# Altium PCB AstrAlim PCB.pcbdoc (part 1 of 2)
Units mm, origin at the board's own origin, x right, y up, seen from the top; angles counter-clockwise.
Board outline 112.02 x 78.49 mm, 4 copper layers (Top Layer, Inner1, Inner2, Bottom Layer); 151 components, 74 nets, 446 pads, 97 vias.
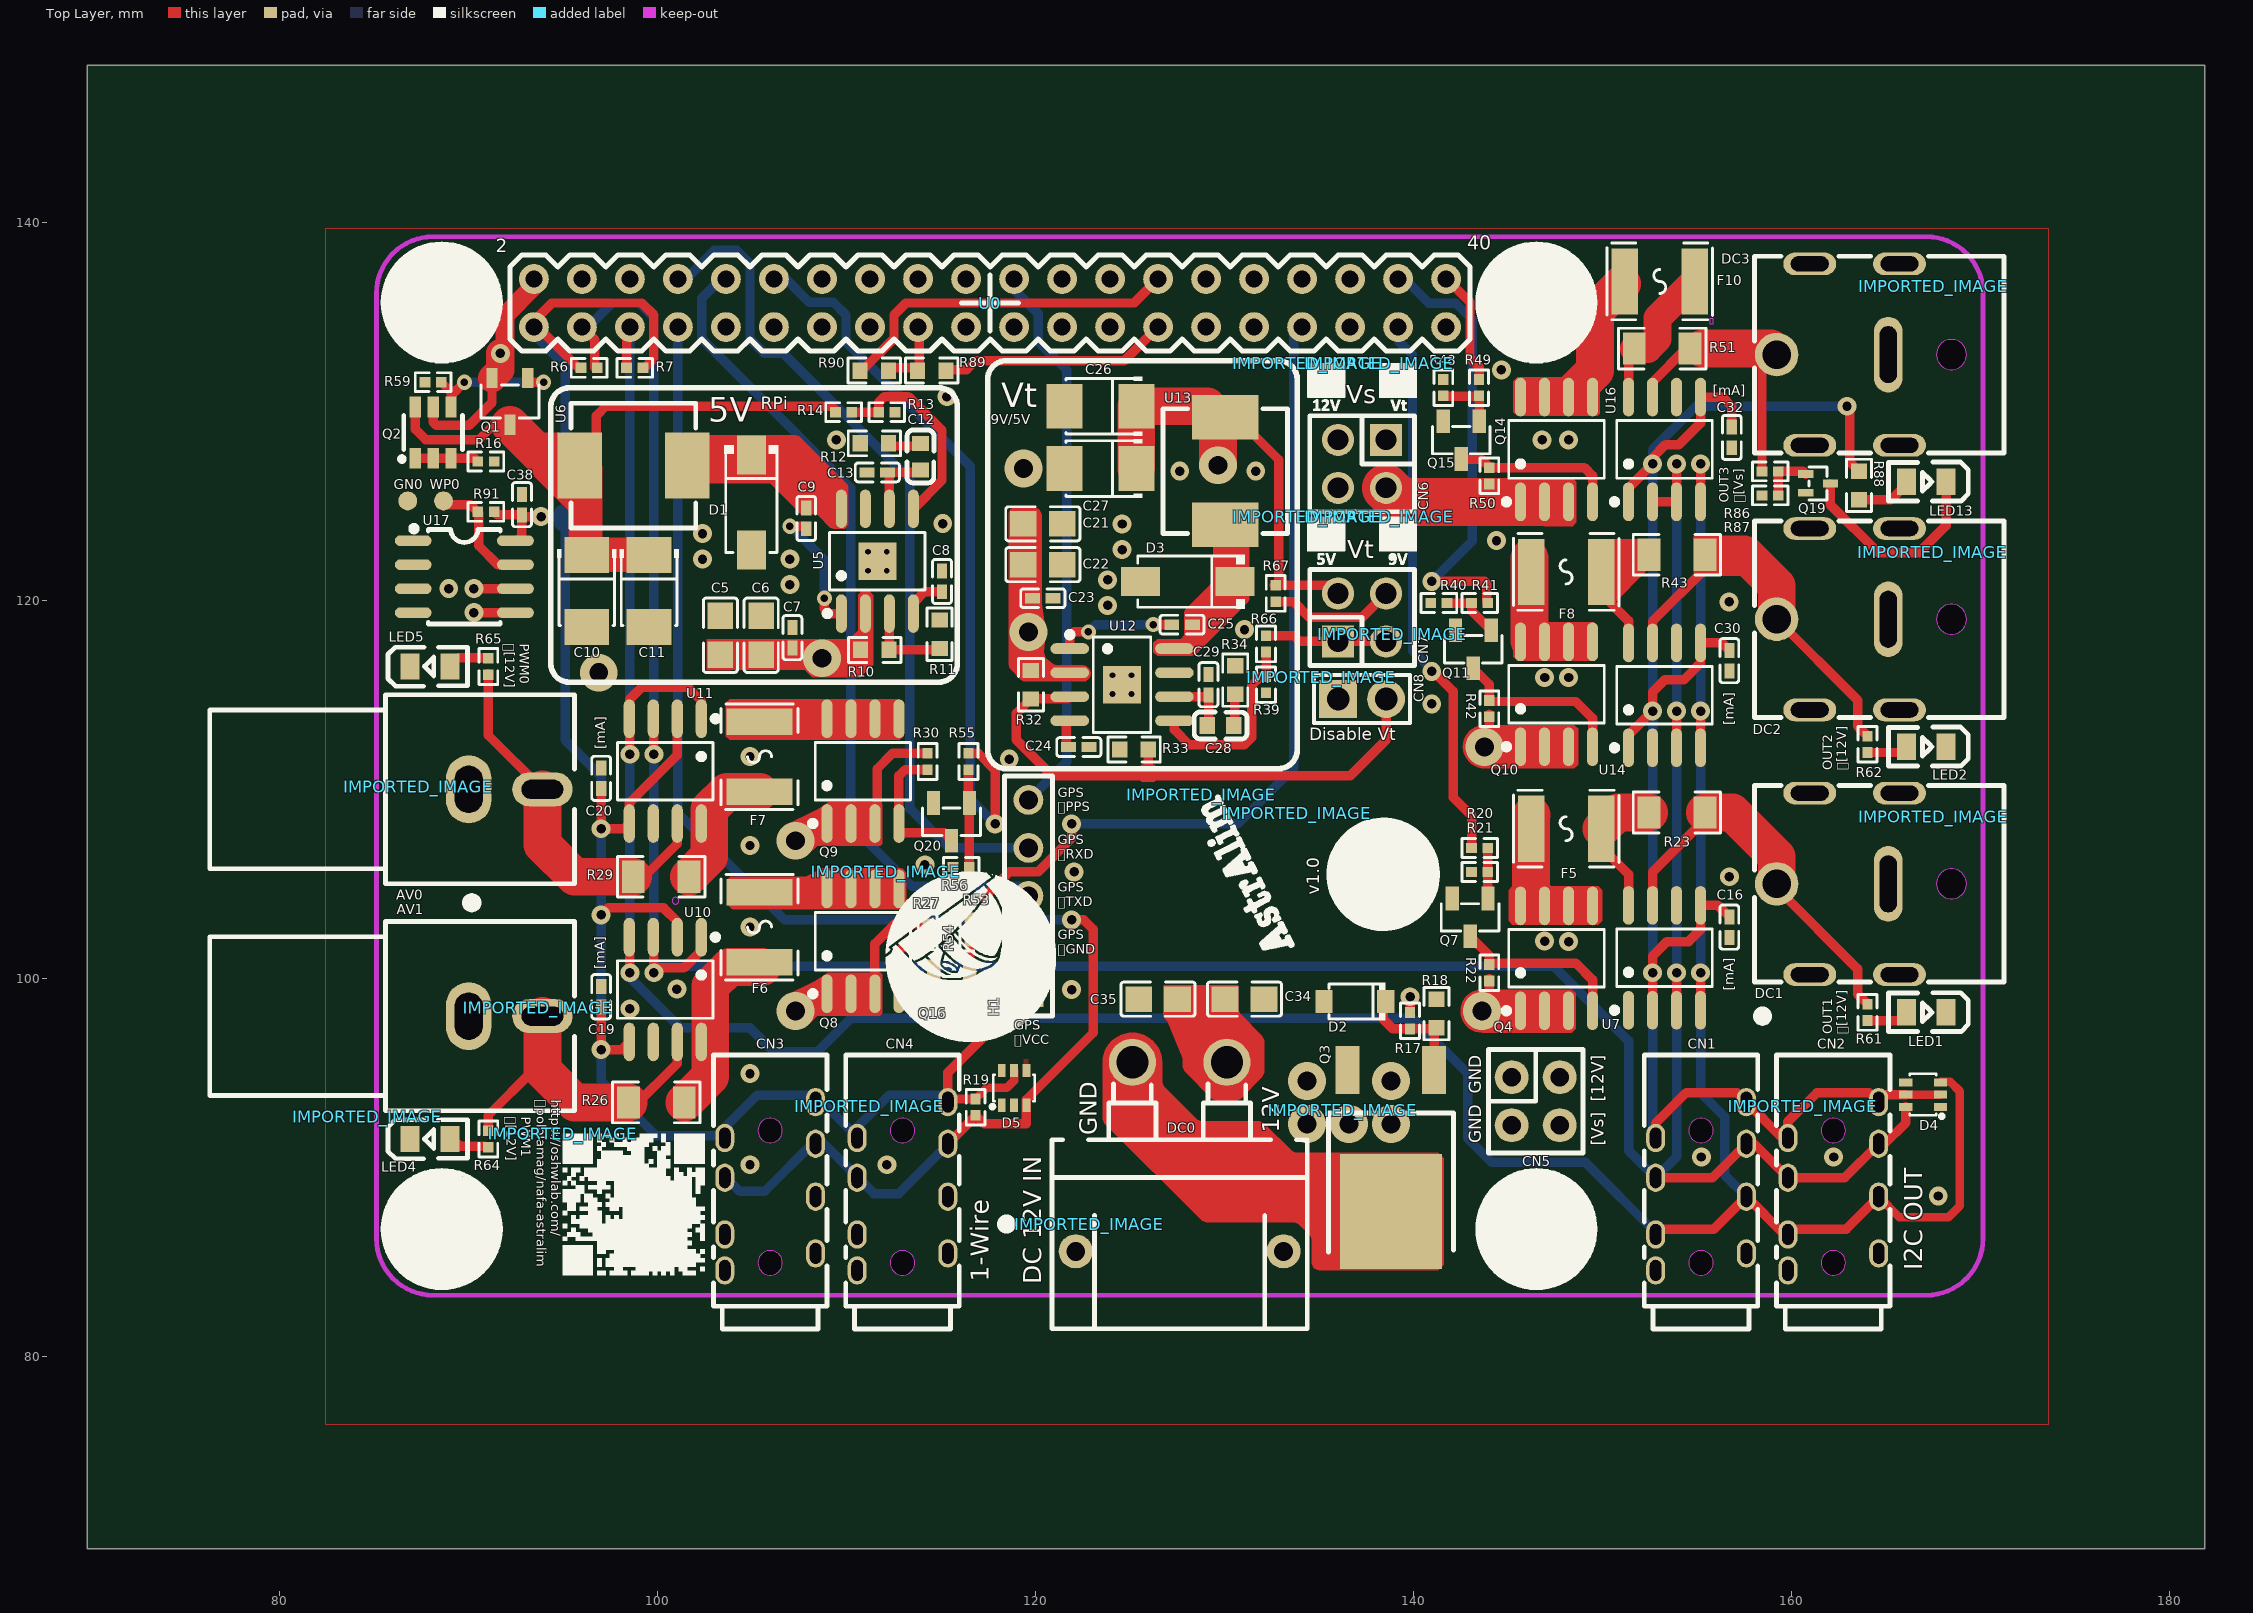
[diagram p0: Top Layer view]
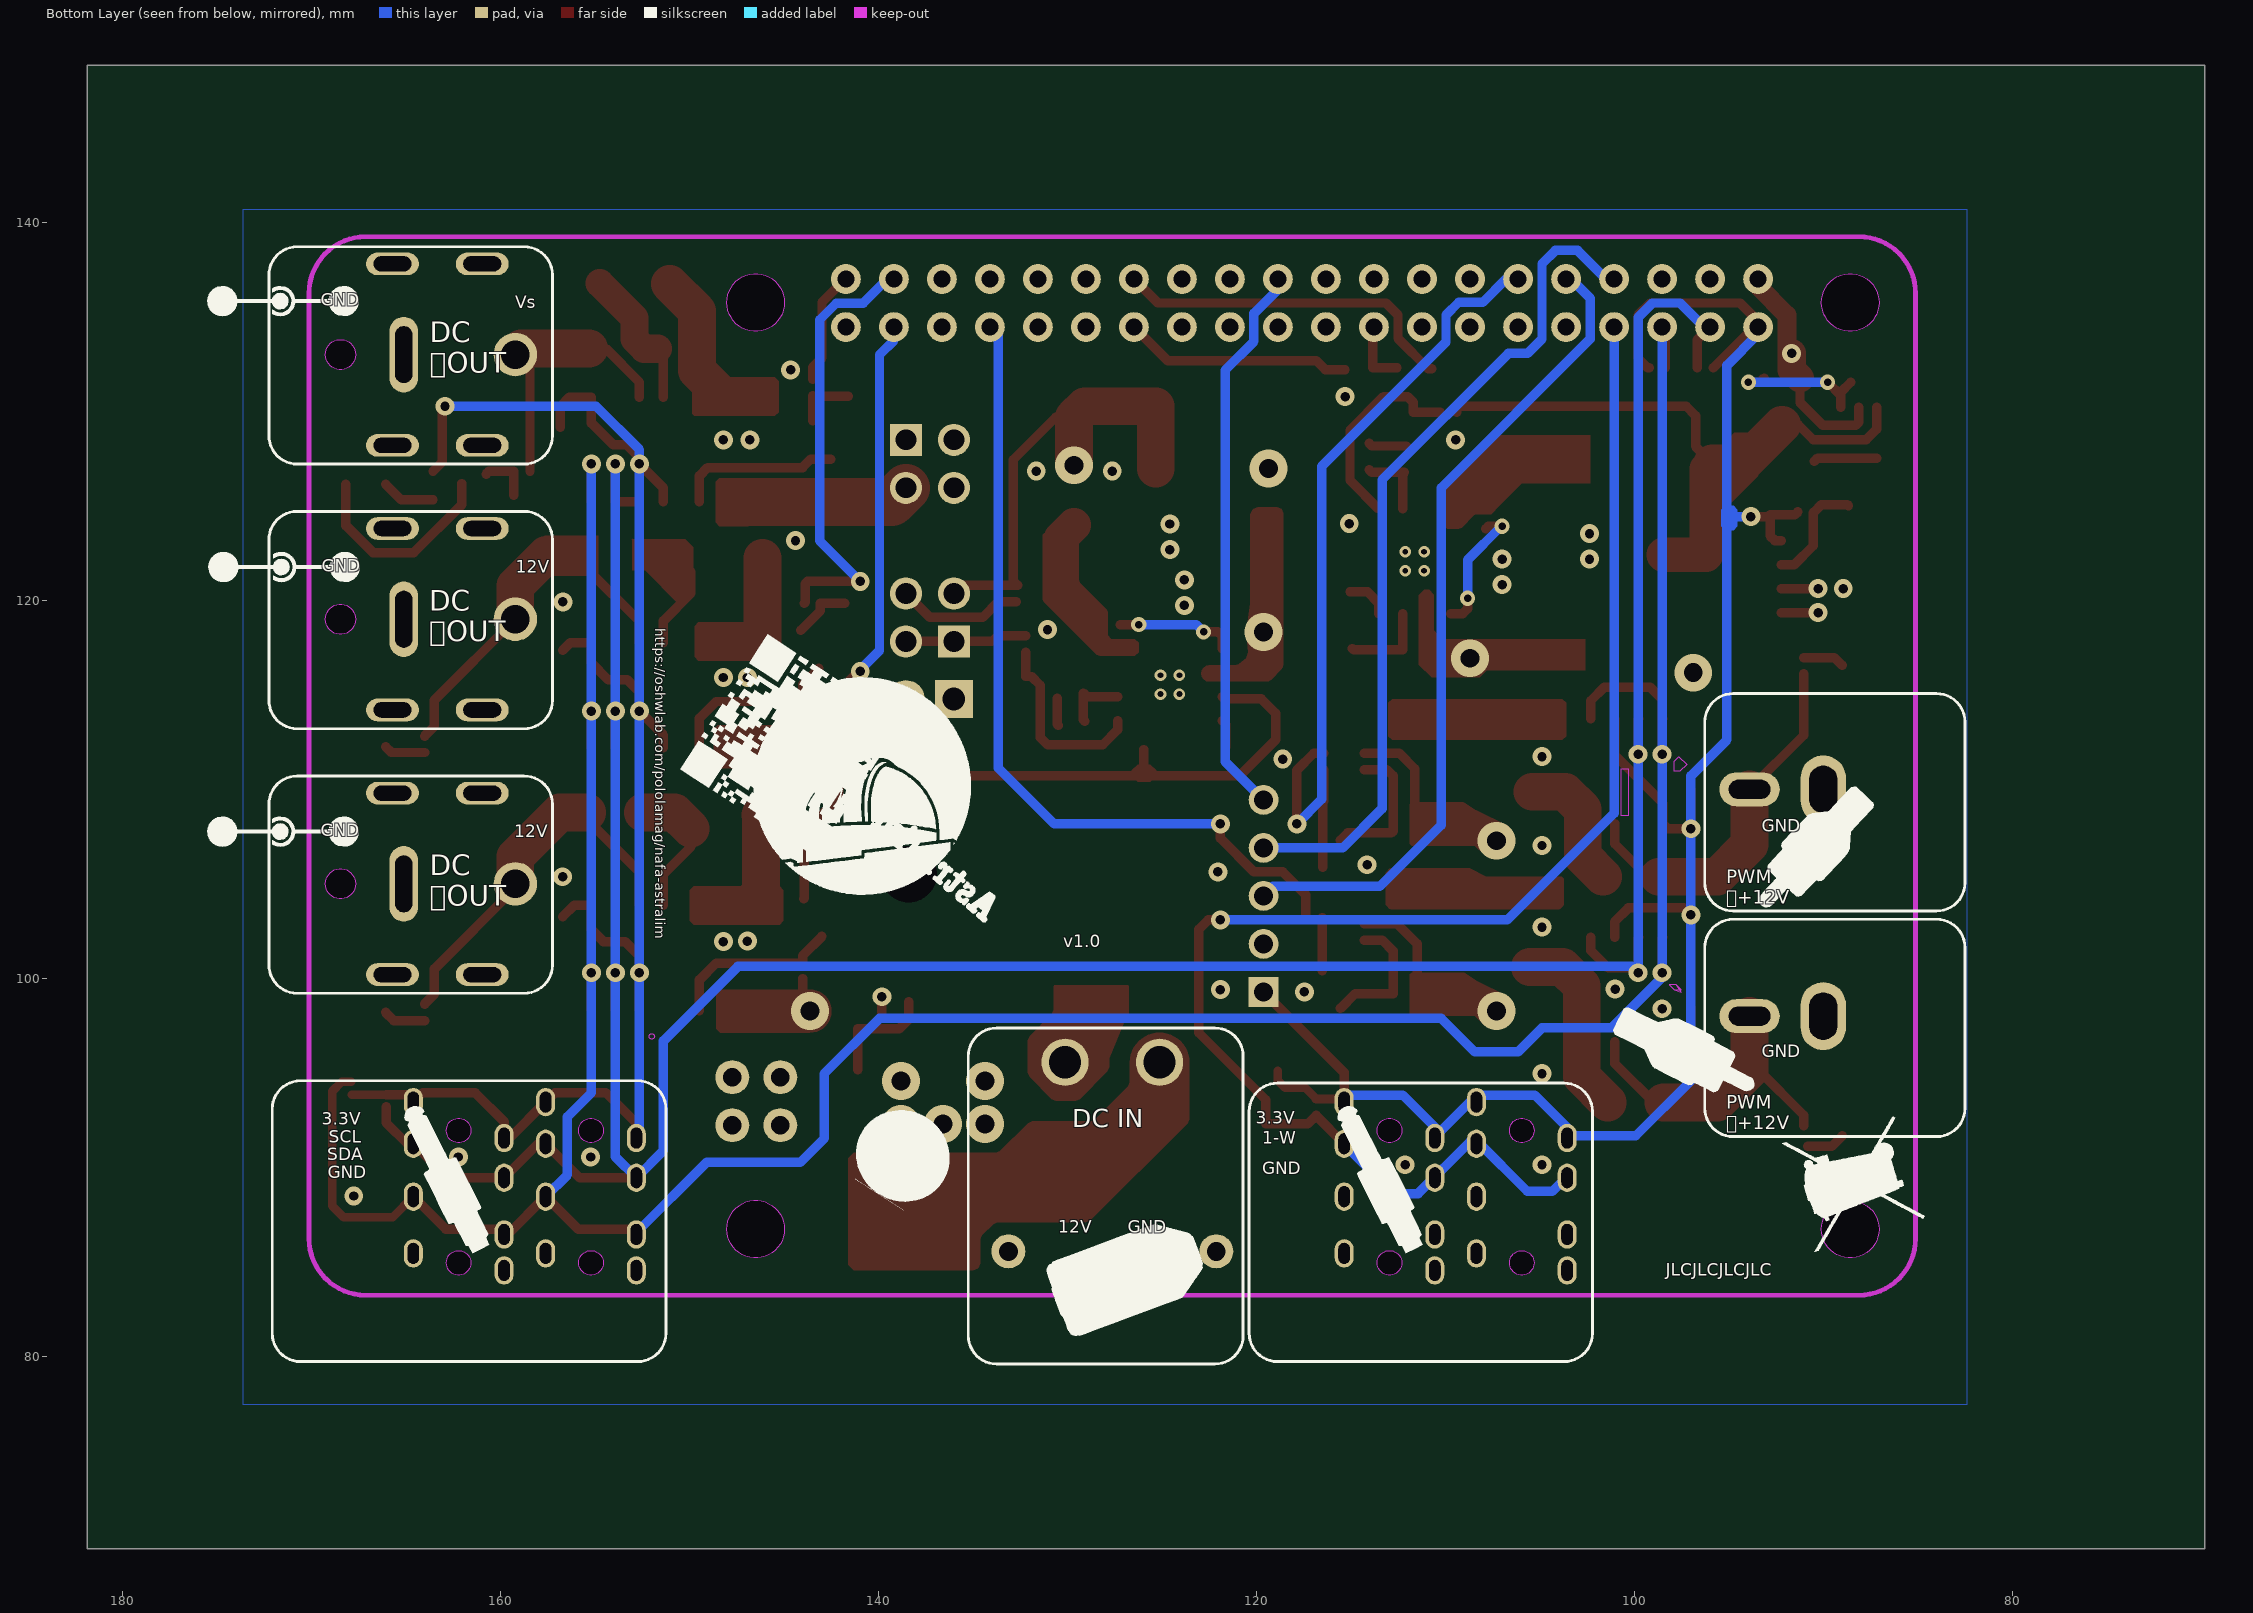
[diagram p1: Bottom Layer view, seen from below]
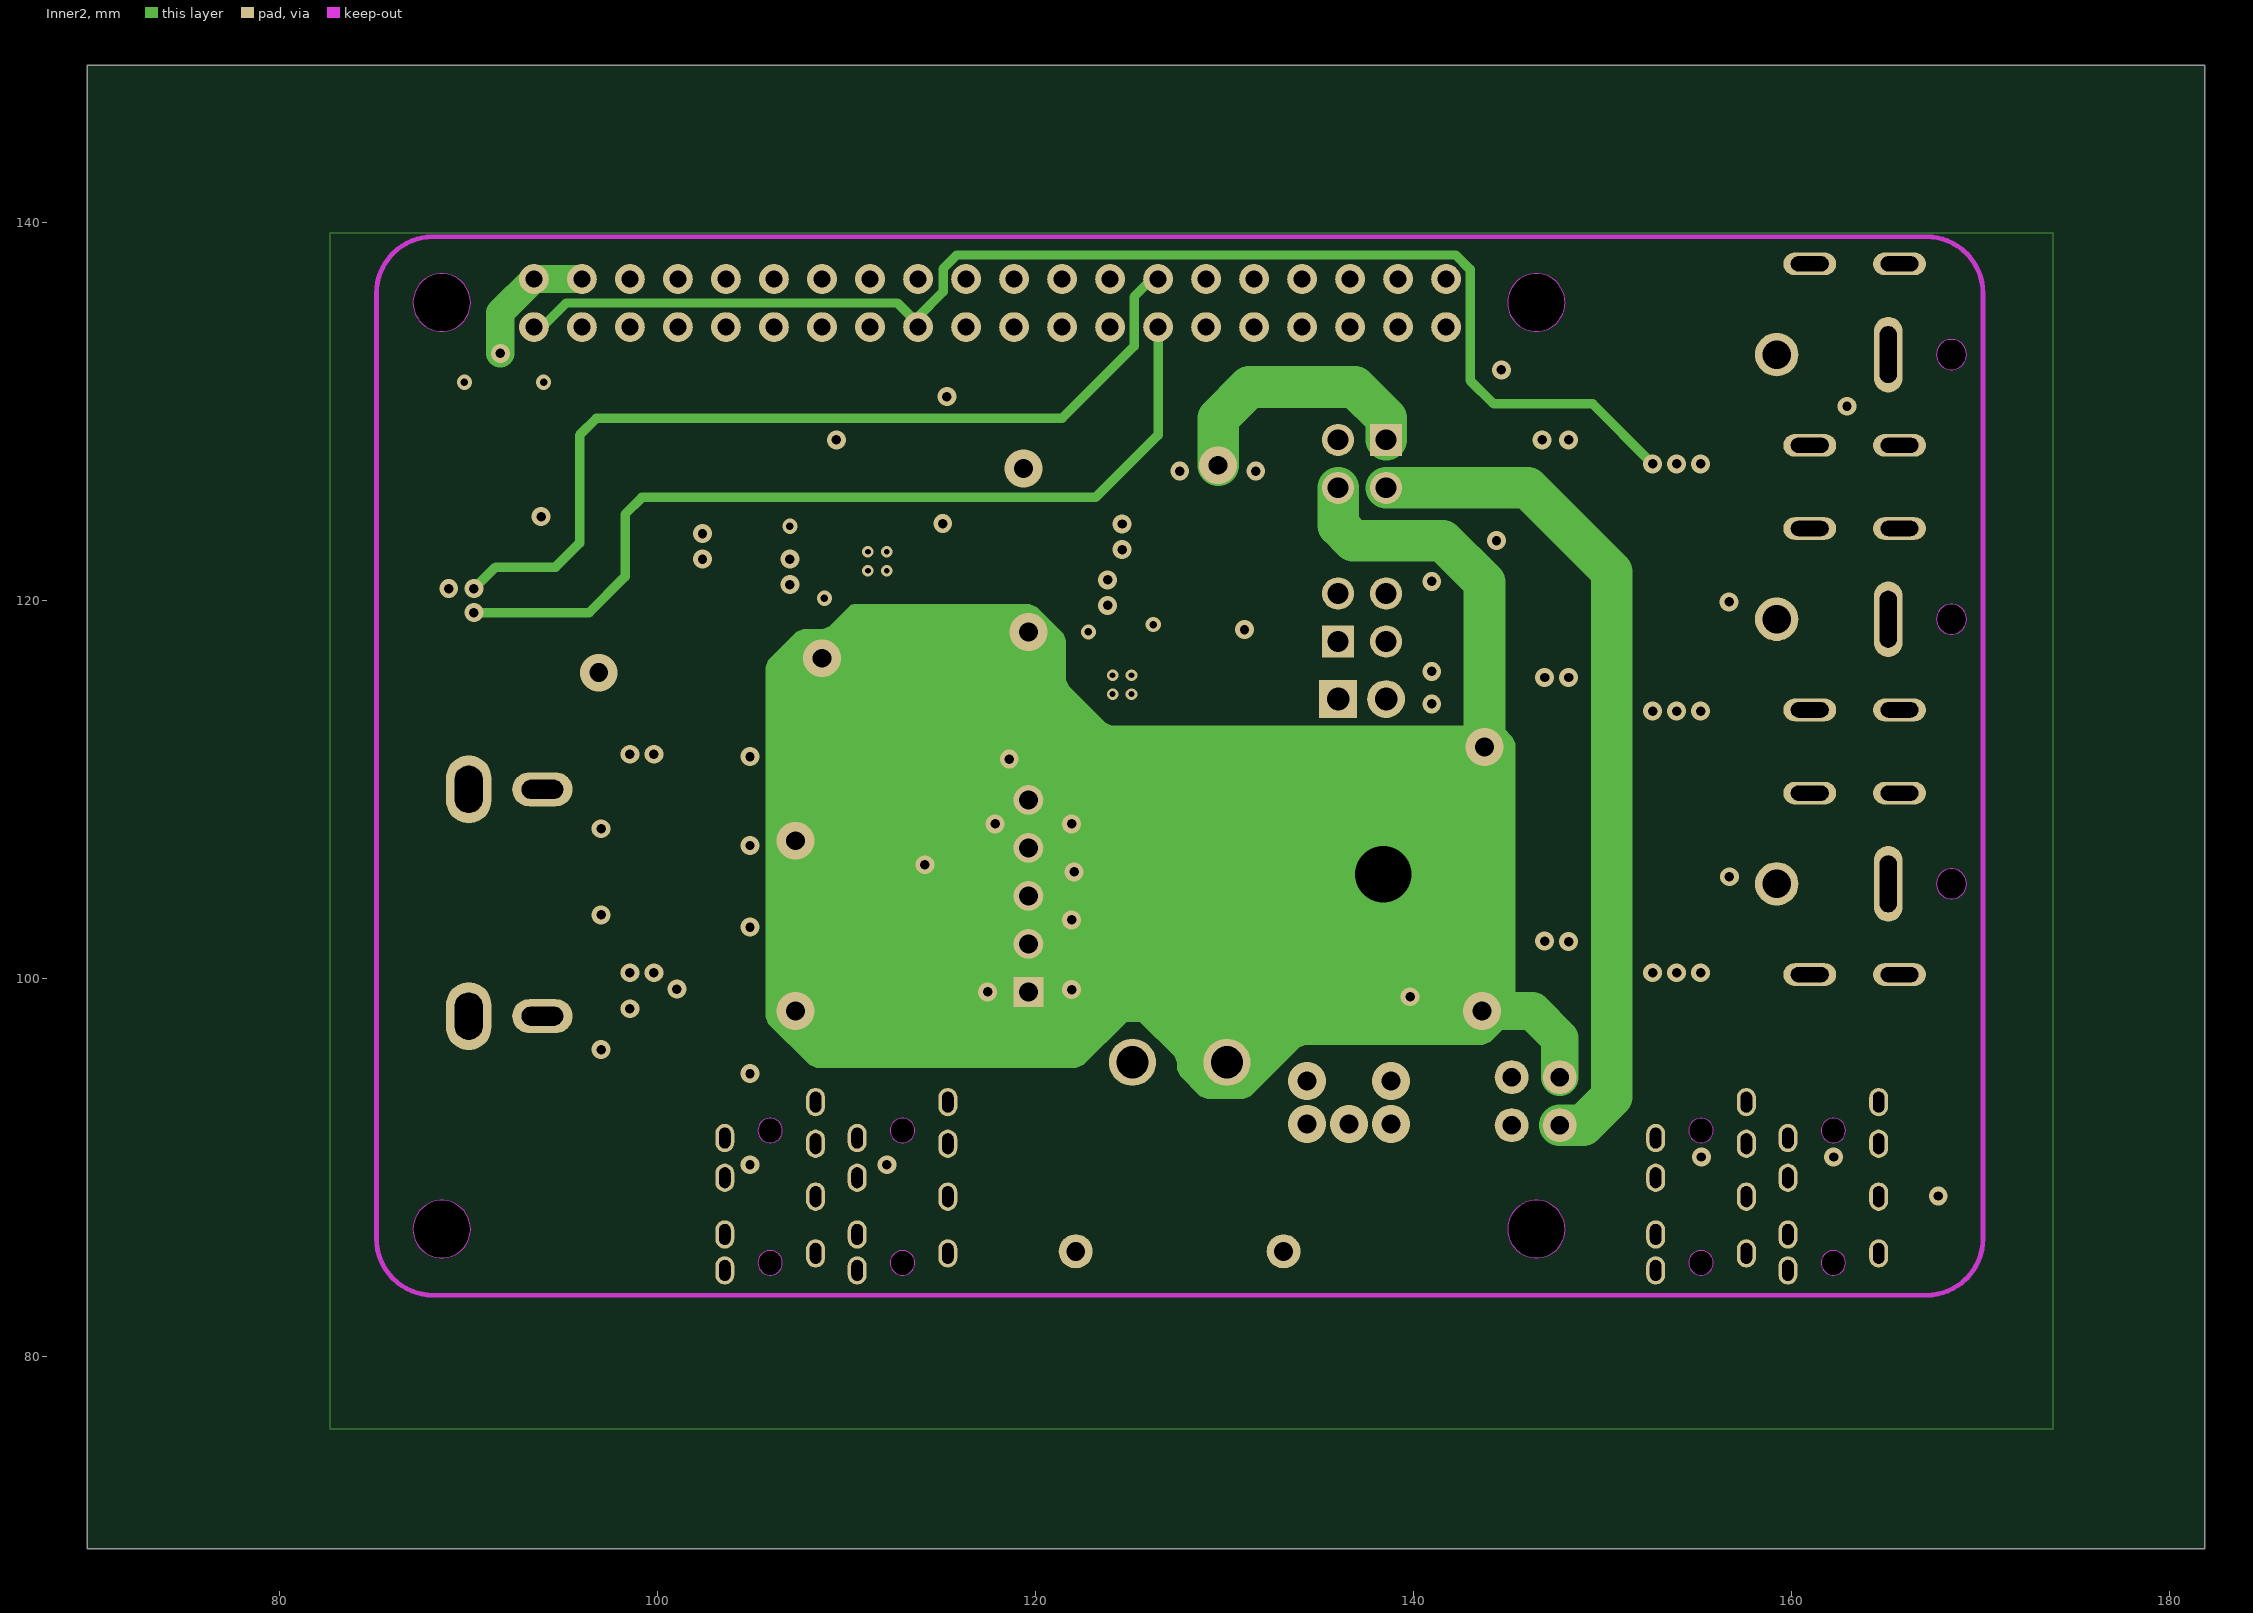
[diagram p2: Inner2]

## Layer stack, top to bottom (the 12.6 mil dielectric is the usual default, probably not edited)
Top Layer: signal copper (thickness not stored)
Dielectric: dielectric 0.32, FR-4, Dk 4.8
Inner1: signal copper (thickness not stored)
Dielectric: dielectric 0.32, FR-4, Dk 4.8
Inner2: signal copper (thickness not stored)
Dielectric: dielectric 0.32, FR-4, Dk 4.8
Bottom Layer: signal copper (thickness not stored)

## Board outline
181.868,69.85 69.85,69.85 69.85,148.336 181.868,148.336

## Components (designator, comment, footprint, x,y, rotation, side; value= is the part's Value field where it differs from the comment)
AV0 "AV-5" CONN-TH_AV-5 91.977,110.033 r270 top
AV1 "AV-5" CONN-TH_AV-5 91.977,98.033 r270 top
C5 "CL21A475KAQNNNE" C0805 103.342,118.185 r270 top
C6 "CL21A475KAQNNNE" C0805 105.501,118.185 r270 top
C7 "CL05B103KB5NNNC" C0402 107.152,118.058 r270 top
C8 "CL05B103KB5NNNC" C0402 115.067,121.031 r270 top
C9 "CL05B103KB5NNNC" C0402 107.884,124.364 r90 top
C10 "CA45-B-16V-47uF-K" CAP-SMD_L3.5-W2.8-R-RD 96.271,120.523 r90 top
C11 "CA45-B-16V-47uF-K" CAP-SMD_L3.5-W2.8-R-RD 99.573,120.523 r90 top
C12 "0603B222K500NT" C0603 113.924,127.635 r270 top
C13 "0402CG220J500NT" C0402 111.646,126.801 r0 top
C16 "CL05B104KO5NNNC" C0402 156.723,102.743 r270 top
C19 "CL05B104KO5NNNC" C0402 97.033,99.06 r90 top
C20 "CL05B104KO5NNNC" C0402 97.033,110.617 r90 top
C21 "CL21A475KAQNNNE" C0805 120.401,124.079 r180 top
C22 "CL21A475KAQNNNE" C0805 120.401,121.92 r180 top
C23 "CL05B103KB5NNNC" C0402 120.401,120.142 r180 top
C24 "CL05B103KB5NNNC" C0402 122.306,112.268 r180 top
C25 "CL05B103KB5NNNC" C0402 127.767,118.745 r0 top
C26 "CA45-B-16V-47uF-K" CAP-SMD_L3.5-W2.8-R-RD 123.449,130.302 r0 top
C27 "CA45-B-16V-47uF-K" CAP-SMD_L3.5-W2.8-R-RD 123.449,127 r0 top
C28 "0603B222K500NT" C0603 129.799,113.411 r180 top
C29 "0402CG220J500NT" C0402 129.164,115.57 r270 top
C30 "CL05B104KO5NNNC" C0402 156.723,116.84 r270 top
C32 "CL05B104KO5NNNC" C0402 156.85,128.651 r270 top
C34 "CL21A226MAQNNNE_C45783" C0805 131.069,98.933 r180 top
C35 "CL21A226MAQNNNE_C45783" C0805 126.497,98.933 r0 top
C38 "CL05B104KO5NNNC" C0402 92.842,125.095 r270 top
CN1 "PJ-35372" AUDIO-TH_PJ-35372 155.223,89.033 r180 top
CN2 "PJ-35372" AUDIO-TH_PJ-35372 162.223,89.033 r180 top
CN3 "PJ-35372" AUDIO-TH_PJ-35372 105.977,89.033 r180 top
CN4 "PJ-35372" AUDIO-TH_PJ-35372 112.977,89.033 r180 top
CN5 "2.54-2*2" HDR-TH_4P-P2.54-V-F-R2-C2-S2.54 146.477,93.533 r270 top
CN6 "PH-00068" HDR-TH_4P-P2.54-V-M-R2-C2-S2.54 137.292,127.254 r180 top
CN7 "PH-00068" HDR-TH_4P-P2.54-V-M-R2-C2-S2.54 137.292,119.126 r0 top
CN8 "PZ254V-11-02P" HDR-TH_2P-P2.54-V-M 137.292,114.808 r0 top
D1 "SS54_C22452" SMA_L4.4-W2.8-LS5.4-R-RD 104.981,125.206 r270 top
D2 "MM1Z15_C86235" SOD-123_L2.7-W1.6-LS3.7-RD 136.911,98.806 r180 top
D3 "SS54_C22452" SMA_L4.4-W2.8-LS5.4-R-RD 128.066,121.022 r180 top
D4 "BAV99S,115" SOT-363_L2.0-W1.3-P0.65-LS2.1-TL 166.971,93.881 r180 top
D5 "BAV99S,115" SOT-363_L2.0-W1.3-P0.65-LS2.1-TL 118.877,94.234 r90 top
DC0 "XT30PW-F" CONN-TH_XT30PW-F-1 127.64,93.091 r0 top
DC1 "DC-053D-25A" DC-IN-TH_DC-053D-25A-1 162.477,105.033 r270 top
DC2 "DC-053D-25A" DC-IN-TH_DC-053D-25A-1 162.477,119.033 r270 top
DC3 "DC-053D-25A" DC-IN-TH_DC-053D-25A-1 162.477,133.033 r270 top
F5 "SMD1812P300SLR/24_C2892380" F1812 148.087,107.95 r180 top
F6 "SMD1812P300SLR/24_C2892380" F1812 105.415,102.743 r90 top
F7 "SMD1812P300SLR/24_C2892380" F1812 105.415,111.76 r90 top
F8 "SMD1812P300SLR/24_C2892380" F1812 148.087,121.539 r180 top
F10 "SMD1812P300SLR/24_C2892380" F1812 153.04,136.906 r180 top
GN0 "Test-Point" test-point-0.5mm 86.803,125.29 r180 top
H1 "2.54-1*5P母" HDR-TH_5P-P2.54-V-F 119.639,104.394 r90 top
IMPORTED_IMAGE "IMPORTED_IMAGE" IMPORTED_IMAGE 128.787,109.753 r0 top
IMPORTED_IMAGE "IMPORTED_IMAGE" IMPORTED_IMAGE 112.083,105.684 r0 top
IMPORTED_IMAGE "IMPORTED_IMAGE" IMPORTED_IMAGE 134.395,132.588 r0 top
IMPORTED_IMAGE "IMPORTED_IMAGE" IMPORTED_IMAGE 138.189,124.46 r0 top
IMPORTED_IMAGE "IMPORTED_IMAGE" IMPORTED_IMAGE 134.395,124.46 r0 top
IMPORTED_IMAGE "IMPORTED_IMAGE" IMPORTED_IMAGE 138.189,132.588 r0 top
IMPORTED_IMAGE "IMPORTED_IMAGE" IMPORTED_IMAGE 133.828,108.774 r0 top
IMPORTED_IMAGE "IMPORTED_IMAGE" IMPORTED_IMAGE 111.217,93.276 r0 top
IMPORTED_IMAGE "IMPORTED_IMAGE" IMPORTED_IMAGE 160.595,93.276 r0 top
IMPORTED_IMAGE "IMPORTED_IMAGE" IMPORTED_IMAGE 87.358,110.182 r0 top
IMPORTED_IMAGE "IMPORTED_IMAGE" IMPORTED_IMAGE 93.668,98.486 r0 top
IMPORTED_IMAGE "IMPORTED_IMAGE" IMPORTED_IMAGE 167.518,108.585 r0 top
IMPORTED_IMAGE "IMPORTED_IMAGE" IMPORTED_IMAGE 167.518,136.652 r0 top
IMPORTED_IMAGE "IMPORTED_IMAGE" IMPORTED_IMAGE 167.461,122.584 r0 top
IMPORTED_IMAGE "IMPORTED_IMAGE" IMPORTED_IMAGE 135.133,115.951 r0 top
IMPORTED_IMAGE "IMPORTED_IMAGE" IMPORTED_IMAGE 84.667,92.718 r0 top
IMPORTED_IMAGE "IMPORTED_IMAGE" IMPORTED_IMAGE 122.849,87.036 r0 top
IMPORTED_IMAGE "IMPORTED_IMAGE" IMPORTED_IMAGE 138.884,118.229 r0 top
IMPORTED_IMAGE "IMPORTED_IMAGE" IMPORTED_IMAGE 95.001,91.821 r0 top
IMPORTED_IMAGE "IMPORTED_IMAGE" IMPORTED_IMAGE 136.257,93.052 r0 top
LED1 "NCD0805R1_C84256" LED0805-R-RD 167.137,98.233 r180 top
LED2 "NCD0805R1_C84256" LED0805-R-RD 167.137,112.287 r180 top
LED4 "NCD0805R1_C84256" LED0805-R-RD 87.977,91.533 r0 top
LED5 "NCD0805R1_C84256" LED0805-R-RD 87.977,116.533 r0 top
LED13 "NCD0805R1_C84256" LED0805-R-RD 167.137,126.303 r180 top
Q1 "DMMT5401-7-F" SOT-23-6_L2.9-W1.6-P0.95-LS2.8-BR 88.143,128.905 r270 top
Q2 "AP2317A" SOT-23-3_L2.9-W1.6-P1.90-LS2.8-BR 92.207,130.556 r90 top
Q3 "IRFR1205TRPBF" TO-252-3_L6.5-W5.8-P4.58-BL 138.816,91.44 r180 top
Q4 "NCE30P12S" SOIC-8_L4.9-W3.9-P1.27-LS6.0-BL 147.579,101.092 r0 top
Q7 "MMBT3904_C20526" SOT-23-3_L2.9-W1.3-P1.90-LS2.4-BR 143.009,103.255 r90 top
Q8 "NCE30P12S" SOIC-8_L4.9-W3.9-P1.27-LS6.0-BL 110.883,101.992 r0 top
Q9 "NCE30P12S" SOIC-8_L4.9-W3.9-P1.27-LS6.0-BL 110.883,110.998 r0 top
Q10 "NCE30P12S" SOIC-8_L4.9-W3.9-P1.27-LS6.0-BL 147.579,115.062 r0 top
Q11 "MMBT3904_C20526" SOT-23-3_L2.9-W1.3-P1.90-LS2.4-BR 143.177,117.449 r90 top
Q14 "NCE30P12S" SOIC-8_L4.9-W3.9-P1.27-LS6.0-BL 147.579,128.016 r0 top
Q15 "MMBT3904_C20526" SOT-23-3_L2.9-W1.3-P1.90-LS2.4-BR 142.54,128.511 r90 top
Q16 "MMBT3904_C20526" SOT-23-3_L2.9-W1.3-P1.90-LS2.4-BR 115.579,99.399 r90 top
Q19 "MMBT3904TT1G" SC-75-3_L1.6-W0.8-P1.00-LS1.6-BR 161.422,126.215 r180 top
Q20 "MMBT3904_C20526" SOT-23-3_L2.9-W1.3-P1.90-LS2.4-BR 115.568,108.311 r90 top
R6 "0402WGF1002TCE" R0402 96.398,132.334 r180 top
R7 "0402WGF1002TCE" R0402 98.811,132.334 r0 top
R10 "AC0603FR-07665KL" R0603 111.511,117.411 r180 top
R11 "0603WAF1303T5E" R0603 114.94,118.237 r270 top
R12 "0603WAF3902T5E" R0603 111.489,128.34 r180 top
R13 "0402WGF1961TCE" R0402 112.146,129.984 r180 top
R14 "0402WGF1022TCE" R0402 109.86,129.984 r180 top
R16 "0402WGF1002TCE" R0402 90.937,127.381 r180 top
R17 "0402WGF1001TCE" R0402 139.832,97.79 r270 top
R18 "0603WAF4703T5E" R0603 141.229,98.171 r270 top
R19 "0402WGF4701TCE" R0402 116.845,93.218 r90 top
R20 "0402WGF1002TCE" R0402 143.515,105.664 r0 top
R21 "0402WGF1001TCE" R0402 143.515,106.934 r0 top
R22 "0402WGF1001TCE" R0402 144.023,100.33 r270 top
R23 "MFJ06HR010FT" R1206 153.947,108.812 r180 top
R26 "MFJ06HR010FT" R1206 99.954,93.472 r0 top
R27 "0402WGF1001TCE" R0402 114.305,102.489 r90 top
R29 "MFJ06HR010FT" R1206 100.208,105.41 r0 top
R30 "0402WGF1001TCE" R0402 114.305,111.506 r90 top
R32 "AC0603FR-07665KL" R0603 119.766,115.57 r90 top
R33 "0603WAF8202T5E" R0603 125.227,112.141 r0 top
R34 "0603WAF3902T5E" R0603 130.581,115.815 r90 top
R39 "0402WGF1961TCE" R0402 132.212,115.57 r90 top
R40 "0402WGF1002TCE" R0402 141.356,119.888 r0 top
R41 "0402WGF1001TCE" R0402 143.515,119.888 r180 top
R42 "0402WGF1001TCE" R0402 144.023,114.3 r270 top
R43 "MFJ06HR010FT" R1206 153.947,122.443 r180 top
R48 "0402WGF1002TCE" R0402 141.59,131.283 r270 top
R49 "0402WGF1001TCE" R0402 143.472,131.283 r270 top
R50 "0402WGF1001TCE" R0402 144.023,126.619 r270 top
R51 "MFJ06HR010FT" R1206 153.167,133.35 r180 top
R53 "0402WGF1001TCE" R0402 116.972,103.251 r180 top
R54 "0402WGF1002TCE" R0402 116.972,101.981 r180 top
R55 "0402WGF1001TCE" R0402 116.464,111.506 r270 top
R56 "0402WGF1002TCE" R0402 116.083,105.918 r0 top
R59 "0402WGF4702TCE" R0402 88.143,131.572 r0 top
R61 "0402WGF4700TCE" R0402 164.027,98.233 r270 top
R62 "0402WGF4700TCE" R0402 164.027,112.414 r270 top
R64 "0402WGF4700TCE" R0402 91.064,91.533 r270 top
R65 "0402WGF4700TCE" R0402 91.064,116.533 r90 top
R66 "0402WGF1022TCE" R0402 132.212,117.729 r90 top
R67 "0402WGF1002TCE" R0402 132.72,120.396 r90 top
R86 "0402WGF1002TCE" R0402 158.882,126.856 r180 top
R87 "0402WGF1002TCE" R0402 158.882,125.586 r0 top
R88 "0603WAF680JT5E" R0603 163.581,126.111 r270 top
R89 "0603WAF3901T5E" R0603 114.519,132.183 r180 top
R90 "0603WAF3901T5E" R0603 111.479,132.183 r0 top
R91 "0402WGF1001TCE" R0402 90.937,124.714 r0 top
U0 "RASPI HAT FULL" RASBERRYPI-3-HAT-EXT 93.477,137.033 r0 top
U5 "TPS54531DDAR" SOIC-8_L5.0-W4.0-P1.27-LS6.0-BL-EP2.0 111.646,122.102 r0 top
U6 "CYA0630-4.7UH" IND-SMD_L7.2-W6.6_GPSR07X0 98.74,127.158 r180 top
U7 "INA219AIDR" SOIC-8_L4.9-W3.9-P1.27-LS6.0-BL 153.294,101.119 r0 top
U10 "INA219AIDR" SOIC-8_L4.9-W3.9-P1.27-LS6.0-BL 100.426,99.441 r180 top
U11 "INA219AIDR" SOIC-8_L4.9-W3.9-P1.27-LS6.0-BL 100.426,110.998 r180 top
U12 "TPS54531DDAR" SOIC-8_L5.0-W4.0-P1.27-LS6.0-BL-EP2.0 124.592,115.57 r270 top
U13 "CYA0630-4.7UH" IND-SMD_L7.2-W6.6_GPSR07X0 130.053,126.873 r90 top
U14 "INA219AIDR" SOIC-8_L4.9-W3.9-P1.27-LS6.0-BL 153.294,115.004 r0 top
U16 "INA219AIDR" SOIC-8_L4.9-W3.9-P1.27-LS6.0-BL 153.294,128.016 r0 top
U17 "CAT24C32WI-GT3" SOIC-8_L5.0-W4.0-P1.27-LS6.0-BL 89.794,121.285 r270 top
WP0 "Test-Point" test-point-0.5mm 88.692,125.29 r180 top

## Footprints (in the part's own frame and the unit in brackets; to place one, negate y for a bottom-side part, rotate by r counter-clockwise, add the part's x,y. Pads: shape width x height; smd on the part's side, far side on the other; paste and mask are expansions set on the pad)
AUDIO-TH_PJ-35372 [mm]
  oval 1x1.5 hole 0.6 slot 1.1 at 90 deg: 1(-2.4,3.55) 2(-2.4,0.55) 3(-2.4,-2.25) 4(-2.4,-4.45) 5(2.4,4.45) 6(2.4,2.55) 7(2.4,-0.45) 8(2.4,-2.55)
  Multi-Layer board cut-out: -0.65,4.05 -0.586,3.768 -0.405,3.542 -0.145,3.416 0.145,3.416 0.405,3.542 0.586,3.768 0.65,4.05 0.65,4.05 0.586,4.332 0.405,4.558 0.145,4.684 -0.145,4.684 -0.405,4.558 -0.586,4.332 -0.65,4.05
  Multi-Layer board cut-out: -0.65,-2.95 -0.586,-3.232 -0.405,-3.458 -0.145,-3.584 0.145,-3.584 0.405,-3.458 0.586,-3.232 0.65,-2.95 0.65,-2.95 0.586,-2.668 0.405,-2.442 0.145,-2.316 -0.145,-2.316 -0.405,-2.442 -0.586,-2.668 -0.65,-2.95
  Multi-Layer keep-out region: -0.65,4.05 -0.586,3.768 -0.405,3.542 -0.145,3.416 0.145,3.416 0.405,3.542 0.586,3.768 0.65,4.05 0.65,4.05 0.586,4.332 0.405,4.558 0.145,4.684 -0.145,4.684 -0.405,4.558 -0.586,4.332 -0.65,4.05
  Multi-Layer keep-out region: -0.65,-2.95 -0.586,-3.232 -0.405,-3.458 -0.145,-3.584 0.145,-3.584 0.405,-3.458 0.586,-3.232 0.65,-2.95 0.65,-2.95 0.586,-2.668 0.405,-2.442 0.145,-2.316 -0.145,-2.316 -0.405,-2.442 -0.586,-2.668 -0.65,-2.95
  silkscreen extent -3,-6.95 3,7.55
C0402 [mm]
  rect 0.79x0.54 smd: 1(-0.545,0) 2(0.545,0)
  silkscreen extent -1.17,-0.5 1.17,0.5
C0603 [mm]
  rect 0.8x0.9 smd: 1(-0.7,0) 2(0.7,0)
  silkscreen extent -1.41,-0.71 1.39,0.72
C0805 [mm]
  rect 1.41x1.35 smd: 1(-1.03,0) 2(1.03,0)
  silkscreen extent -1.96,-0.9 1.96,0.9
CAP-SMD_L3.5-W2.8-R-RD [mm]
  rect 1.9x2.376 smd: 1(1.899,0) 2(-1.899,0)
  silkscreen extent -1.83,-1.55 2.21,1.55
CONN-TH_AV-5 [mm]
  oval 3.6x2.4 hole 1.5 slot 2.5 at 0 deg: 1(0,-1.95)
  oval 1.8x3.2 hole 1 slot 2.2 at 90 deg copper offset -0.001,0: 2(0.001,1.95)
  silkscreen extent -5,-15.65 5,3.65
CONN-TH_XT30PW-F-1 [mm]
  round 2.5 hole 1.7 copper offset 0,0: 1(-2.5,2.5) 2(2.5,2.5)
  round 1.8 hole 1 copper offset 0,0: 3(5.5,-7.5) 4(-5.5,-7.5)
  silkscreen extent -6.75,-11.6 6.75,1.35
DC-IN-TH_DC-053D-25A-1 [mm]
  round 2.3 hole 1.5: 1(0,-3.25)
  oval 4x1.5 hole 0.914 slot 3 at 0 deg: 2(0,2.65)
  oval 1.2x2.8 hole 0.8 slot 2 at 90 deg: 3(-4.8,3.25) 3(-4.8,-1.5) 3(4.8,3.25) 3(4.8,-1.5)
  Multi-Layer board cut-out: 0,6.8 -0.347,6.721 -0.625,6.499 -0.78,6.178 -0.78,5.822 -0.625,5.501 -0.347,5.279 0,5.2 0,5.2 0.347,5.279 0.625,5.501 0.78,5.822 0.78,6.178 0.625,6.499 0.347,6.721 0,6.8
  Multi-Layer keep-out region: 0,6.8 -0.347,6.721 -0.625,6.499 -0.78,6.178 -0.78,5.822 -0.625,5.501 -0.347,5.279 0,5.2 0,5.2 0.347,5.279 0.625,5.501 0.78,5.822 0.78,6.178 0.625,6.499 0.347,6.721 0,6.8
  silkscreen extent -5.2,-4.43 5.2,8.77
F1812 [mm]
  rect 1.407x3.499 smd: 1(-1.853,0) 2(1.853,0)
  silkscreen extent -2.79,-2.03 2.79,2.03
HDR-TH_2P-P2.54-V-M [mm]
  rect 2x2 hole 1.2: 1(-1.27,0)
  round 2 hole 1.2: 2(1.27,0)
  silkscreen extent -2.54,-1.27 2.54,1.27
HDR-TH_4P-P2.54-V-F-R2-C2-S2.54 [mm]
  round 1.8 hole 1: 1(-1.27,-1.27) 2(-1.27,1.27) 3(1.27,-1.27) 4(1.27,1.27)
  silkscreen extent -2.74,-2.5 2.74,2.5
HDR-TH_4P-P2.54-V-M-R2-C2-S2.54 [mm]
  rect 1.7x1.7 hole 1.1: 1(-1.27,-1.27)
  round 1.7 hole 1.1: 2(-1.27,1.27) 3(1.27,-1.27) 4(1.27,1.27)
  silkscreen extent -2.77,-2.54 2.77,2.54
HDR-TH_5P-P2.54-V-F [mil]
  rect 62x62 hole 40.16: 1(-200,0)
  round 62 hole 40.16: 2(-100,0) 3(0,0) 4(100,0) 5(200,0)
  silkscreen extent -250,-50 250,50
IMPORTED_IMAGE [mm]
  silkscreen extent 0,-8.25 4.93,0
IND-SMD_L7.2-W6.6_GPSR07X0 [mm]
  rect 2.35x3.5 smd: 1(-2.85,0) 2(2.85,0)
  silkscreen extent -3.3,-3.3 3.3,3.3
LED0805-R-RD [mm]
  rect 1x1.4 smd: 1(1.05,0) 2(-1.05,0)
  silkscreen extent -2.22,-1.04 1.99,1.01
R0402 [mm]
  rect 0.566x0.54 smd: 1(-0.433,0) 2(0.433,0)
  silkscreen extent -0.94,-0.5 0.94,0.5
R0603 [mm]
  rect 0.806x0.864 smd: 1(-0.753,0) 2(0.753,0)
  silkscreen extent -1.39,-0.66 1.39,0.66
R1206 [mm]
  rect 1.208x1.701 smd: 1(-1.479,0) 2(1.479,0)
  silkscreen extent -2.31,-1.08 2.31,1.08
RASBERRYPI-3-HAT-EXT [mil]
  round 62 hole 35: 1(0,-100) 2(0,0) 3(100,-100) 4(100,0) 5(200,-100) 6(200,0) 7(300,-100) 8(300,0) 9(400,-100) 10(400,0) 11(500,-100) 12(500,0) 13(600,-100) 14(600,0) 15(700,-100) 16(700,0) 17(800,-100) 18(800,0) 19(900,-100) 20(900,0) 21(1000,-100) 22(1000,0) 23(1100,-100) 24(1100,0) 25(1200,-100) 26(1200,0) 27(1300,-100) 28(1300,0) 29(1400,-100) 30(1400,0) 31(1500,-100) 32(1500,0) 33(1600,-100) 34(1600,0) 35(1700,-100) 36(1700,0) 37(1800,-100) 38(1800,0) 39(1900,-100) 40(1900,0)
  Board Outline Layer lines w10: -210,-2116.61 2900.23,-2116.61 ; -210,-2116.61 2900.23,-2116.61 ; -210,-2116.61 cw(c-210,-1998.5) -328.11,-1998.5 ccw(c-210,-1998.5) -210,-2116.61 ; -210,88.11 2900.23,88.11 ; -210,88.11 2900.23,88.11 ; -210,88.11 ccw(c-210,-30) -328.11,-30 cw(c-210,-30) -210,88.11 ; 2900.24,-2116.61 ccw(c2900.24,-1998.5) 3018.35,-1998.5 ; 2900.24,-2116.61 ccw(c2900.24,-1998.5) 3018.35,-1998.5 ; 2900.24,88.11 cw(c2900.24,-30) 3018.35,-30 ; 2900.24,88.11 cw(c2900.24,-30) 3018.35,-30 ; 3018.35,-1998.51 3018.35,-30 ; 3018.35,-1998.51 3018.35,-30 ; -328,-1998 -328,-29.5 -328,-1998
  Multi-Layer board cut-out: 2148,-49 2142.06,-22.97 2125.41,-2.09 2101.35,9.5 2074.65,9.5 2050.59,-2.09 2033.94,-22.97 2028,-49 2028,-49 2033.94,-75.03 2050.59,-95.91 2074.65,-107.5 2101.35,-107.5 2125.41,-95.91 2142.06,-75.03 2148,-49
  Multi-Layer board cut-out: -132,-49 -137.94,-22.97 -154.59,-2.09 -178.65,9.5 -205.35,9.5 -229.41,-2.09 -246.06,-22.97 -252,-49 -252,-49 -246.06,-75.03 -229.41,-95.91 -205.35,-107.5 -178.65,-107.5 -154.59,-95.91 -137.94,-75.03 -132,-49
  Multi-Layer board cut-out: -132,-1979 -137.94,-1952.97 -154.59,-1932.09 -178.65,-1920.5 -205.35,-1920.5 -229.41,-1932.09 -246.06,-1952.97 -252,-1979 -252,-1979 -246.06,-2005.03 -229.41,-2025.91 -205.35,-2037.5 -178.65,-2037.5 -154.59,-2025.91 -137.94,-2005.03 -132,-1979
  Multi-Layer board cut-out: 2148,-1979 2142.06,-1952.97 2125.41,-1932.09 2101.35,-1920.5 2074.65,-1920.5 2050.59,-1932.09 2033.94,-1952.97 2028,-1979 2028,-1979 2033.94,-2005.03 2050.59,-2025.91 2074.65,-2037.5 2101.35,-2037.5 2125.41,-2025.91 2142.06,-2005.03 2148,-1979
  Multi-Layer keep-out region: 2148,-49 2142.06,-22.97 2125.41,-2.09 2101.35,9.5 2074.65,9.5 2050.59,-2.09 2033.94,-22.97 2028,-49 2028,-49 2033.94,-75.03 2050.59,-95.91 2074.65,-107.5 2101.35,-107.5 2125.41,-95.91 2142.06,-75.03 2148,-49
  Multi-Layer keep-out region: -132,-49 -137.94,-22.97 -154.59,-2.09 -178.65,9.5 -205.35,9.5 -229.41,-2.09 -246.06,-22.97 -252,-49 -252,-49 -246.06,-75.03 -229.41,-95.91 -205.35,-107.5 -178.65,-107.5 -154.59,-95.91 -137.94,-75.03 -132,-49
  Multi-Layer keep-out region: -132,-1979 -137.94,-1952.97 -154.59,-1932.09 -178.65,-1920.5 -205.35,-1920.5 -229.41,-1932.09 -246.06,-1952.97 -252,-1979 -252,-1979 -246.06,-2005.03 -229.41,-2025.91 -205.35,-2037.5 -178.65,-2037.5 -154.59,-2025.91 -137.94,-2005.03 -132,-1979
  Multi-Layer keep-out region: 2148,-1979 2142.06,-1952.97 2125.41,-1932.09 2101.35,-1920.5 2074.65,-1920.5 2050.59,-1932.09 2033.94,-1952.97 2028,-1979 2028,-1979 2033.94,-2005.03 2050.59,-2025.91 2074.65,-2037.5 2101.35,-2037.5 2125.41,-2025.91 2142.06,-2005.03 2148,-1979
  silkscreen extent -314,-2101 2210,73
SC-75-3_L1.6-W0.8-P1.00-LS1.6-BR [mm]
  rect 0.816x0.4 smd: 1(0.65,-0.5) 2(0.65,0.5) 3(-0.65,0)
  silkscreen extent -0.48,-0.88 0.48,0.88
SMA_L4.4-W2.8-LS5.4-R-RD [mm]
  rect 2.063x1.539 smd: 1(2.504,0) 2(-2.504,0)
  silkscreen extent -3.03,-1.43 2.65,1.43
SOD-123_L2.7-W1.6-LS3.7-RD [mm]
  rect 0.91x1.22 smd: 1(-1.635,0) 2(1.635,0)
  silkscreen extent -1.6,-1 1.38,1
SOIC-8_L4.9-W3.9-P1.27-LS6.0-BL [mm]
  oval 0.588x2.045 smd: 1(-1.905,-2.772) 2(-0.635,-2.772) 3(0.635,-2.772) 4(1.905,-2.772) 5(1.905,2.772) 6(0.635,2.772) 7(-0.635,2.772) 8(-1.905,2.772)
  silkscreen extent -2.8,-2.92 2.53,1.52
SOIC-8_L5.0-W4.0-P1.27-LS6.0-BL [mil]
  oval 22.38x76.78 smd: 1(-75,-106.5) 2(-25,-106.5) 3(25,-106.5) 4(75,-106.5) 5(75,106.5) 6(25,106.5) 7(-25,106.5) 8(-75,106.5)
  silkscreen extent -106,-111 98,75
SOIC-8_L5.0-W4.0-P1.27-LS6.0-BL-EP2.0 [mm]
  oval 0.574x2.038 smd: 1(-1.905,-2.769) 2(-0.635,-2.769) 3(0.635,-2.769) 4(1.905,-2.769) 5(1.905,2.769) 6(0.635,2.769) 7(-0.635,2.769) 8(-1.905,2.769)
  rect 2x2 smd: 9(0,0)
  silkscreen extent -2.79,-2.92 2.53,1.52
SOT-23-3_L2.9-W1.3-P1.90-LS2.4-BR [mm]
  rect 1.25x0.7 smd: 1(1,-0.95) 2(1,0.95) 3(-1,0)
  silkscreen extent -0.73,-1.53 0.73,1.53
SOT-23-3_L2.9-W1.6-P1.90-LS2.8-BR [mm]
  rect 1.07x0.6 smd: 1(1.235,-0.95) 2(1.235,0.95) 3(-1.235,0)
  silkscreen extent -0.88,-1.54 0.88,1.54
SOT-23-6_L2.9-W1.6-P0.95-LS2.8-BR [mm]
  rect 1.1x0.6 smd: 1(1.35,-0.95) 2(1.35,0) 3(1.35,0.95) 4(-1.35,0.95) 5(-1.35,0) 6(-1.35,-0.95)
  silkscreen extent -0.9,-1.78 1.52,1.55
SOT-363_L2.0-W1.3-P0.65-LS2.1-TL [mm]
  rect 0.7x0.42 smd: 1(-0.92,0.65) 2(-0.92,0) 3(-0.92,-0.65) 4(0.92,-0.65) 5(0.92,0) 6(0.92,0.65)
  silkscreen extent -1.09,-1.1 0.7,1.24
test-point-0.5mm [mm]
  round 1 smd: 1(0,0)
TO-252-3_L6.5-W5.8-P4.58-BL [mm]
  rect 1.27x2.54 smd: 1(-2.288,-3.747) 3(2.288,-3.745)
  rect 5.4x6.1 smd: 2(-0.002,3.747)
  silkscreen extent -3.31,-1.46 3.3,5.9

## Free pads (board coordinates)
  round 1.524 hole 3: 41(138.409,105.534)

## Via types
v1: diameter 1, hole 0.5, Top Layer to Bottom Layer, 69 vias
v2: diameter 2, hole 1, Top Layer to Bottom Layer, 14 vias
v3: diameter 0.61, hole 0.305, Top Layer to Bottom Layer, 8 vias
v4: diameter 0.8, hole 0.4, Top Layer to Bottom Layer, 6 vias

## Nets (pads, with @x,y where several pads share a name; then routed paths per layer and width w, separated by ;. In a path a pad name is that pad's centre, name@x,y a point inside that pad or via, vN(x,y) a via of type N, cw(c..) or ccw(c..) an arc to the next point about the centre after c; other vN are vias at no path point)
1-WIRE: CN3.3 CN3.7 CN4.3 CN4.7 D5.3 R19.1 U0.7 | length 82.6
  Top Layer w0.5: CN4.3@115.377,91.283 116.845,92.751 R19.1@116.845,92.785 117.301,92.329 119.512,92.329 119.527,92.344 D5.3@119.527,93.314 119.527,93.614 123.068,97.155 123.068,102.624 122.568,103.124 v1(121.925,103.124)
  Bottom Layer w0.5: U0.7@101.097,134.493 101.097,108.769 106.742,103.124 v1(121.925,103.124) ; CN3.7@103.523,89.604 104.354,88.773 105.692,88.773 108.323,91.404 108.708,91.404 111.466,88.646 112.781,88.646 115.308,91.173 CN4.3@115.308,91.404
$1N4635: R10.1 R11.2 U5.3 | length 4.6
  Top Layer w0.5: U5.3@112.281,119.333 112.281,117.428 R10.1@112.264,117.411 114.868,117.411 R11.2@114.94,117.484
$1N4659: C8.2 U5.4 | length 2.3
  Top Layer w0.5: U5.4@113.551,119.333 113.551,119.896 114.141,120.486 C8.2@115.067,120.486
$1N4694: C9.1 U5.1 | length 7
  Top Layer w0.5: v4@107.066,123.952 107.751,123.952 C9.1@107.884,123.819 ; v4(108.844,120.142) 108.844,119.587 109.098,119.333 U5.1@109.741,119.333
  Bottom Layer w0.5: v4@107.066,123.952 108.844,122.174 v4(108.844,120.142)
  other v4: 107.021,123.952
$1N4920: C9.2 D1.2 U5.8 U6.1
$1N5140: C12.1 R12.1 | length 2
  Top Layer w0.5: R12.1@112.079,128.198 113.914,128.198 C12.1@114.051,128.335
$1N5148: C12.2 C13.2 U5.6 | length 3.9
  Top Layer w0.5: U5.6@112.281,124.872 112.281,126.712 C13.2@112.191,126.801 113.918,126.801 C12.2@114.051,126.935
$1N5310: R13.2 R14.1 U5.5 | length 10.9
  Top Layer w0.5: R14.1@110.293,129.984 R13.2@111.713,129.984 111.713,130.505 112.019,130.81 113.289,130.81 115.067,129.032 115.067,126.388 U5.5@113.551,124.872
$1N7006: Q1.4 Q2.1 R59.2 | length 7.6
  Top Layer w0.5: R59.2@88.576,131.572 89.093,131.055 89.093,130.871 ; Q1.4@89.093,130.255 89.093,130.871 ; v4(89.794,131.572) 89.093,130.871 ; Q2.1@93.157,131.791 93.376,131.572 v4(93.985,131.572)
  Bottom Layer w0.5: v4(89.794,131.572) v4(93.985,131.572)
$1N7063: Q1.1 Q1.2 Q1.3 R16.2 | length 3.4
  Top Layer w0.5: Q1.1@87.193,127.555 Q1.2@88.143,127.555 Q1.3@89.093,127.555 90.33,127.555 R16.2@90.504,127.381
$1N14594: C24.2 U12.4 | length 1.5
  Top Layer w0.5: C24.2@121.634,112.268 121.634,113.476 U12.4@121.823,113.665
$1N14595: C25.1 U12.1 | length 6.3
  Top Layer w0.5: U12.1@121.823,117.475 121.823,118.135 122.052,118.364 v4(122.814,118.364) ; v4(126.243,118.745) C25.1@127.222,118.745
  Bottom Layer w0.5: v4(122.814,118.364) 123.195,118.745 v4(126.243,118.745)
$1N14596: C25.2 D3.2 U12.8 U13.1 | length 3.2
  Top Layer w1.8: U13.1@129.672,124.023 130.362,123.333 D3.2@130.362,121.158
$1N14599: C28.1 R34.1 | length 1.5
  Top Layer w0.5: C28.1@130.499,113.411 130.564,113.476 R34.1@130.564,114.859
$1N14601: C28.2 C29.2 U12.6 | length 3.4
  Top Layer w0.5: U12.6@127.361,114.935 128.974,114.935 129.167,115.128 129.167,113.706 C28.2@129.102,113.641
$1N14603: R39.2 R66.1 U12.5 | length 10.1
  Top Layer w0.5: U12.5@127.361,113.665 127.361,113.182 128.148,112.395 131.069,112.395 131.45,112.776 131.45,115.544 131.909,116.003 R39.2@132.212,116.003 R66.1@132.212,117.296
$1N50988: CN7.4 R67.1 | length 6.7
  Top Layer w0.5: R67.1@132.72,119.963 133.661,119.963 134.498,119.126 137.292,119.126 CN7.4@138.562,120.396
$1N55064: CN7.1 CN7.3 R66.2 | length 6.5
  Top Layer w0.5: R66.2@132.212,118.162 133.684,118.162 133.99,117.856 CN7.1@136.022,117.856 CN7.3@138.562,117.856
$1N55959: D2.1 Q3.1 R17.2 R18.2 | length 6
  Top Layer w0.5: D2.1@138.419,98.806 138.419,97.857 138.919,97.357 R17.2@139.832,97.357 141.102,97.357 141.102,95.189 Q3.1@141.104,95.187
$1N59627: CN8.2 R32.1 R33.2 U12.3 | length 29.3
  Top Layer w0.5: U12.3@121.823,114.935 121.705,114.817 R32.1@119.766,114.817 119.004,114.055 119.004,112.649 120.909,110.744 125.98,110.744 ; R33.2@125.98,112.141 125.98,110.744 ; CN8.2@138.562,114.808 138.562,112.649 136.657,110.744 125.98,110.744
$1N62787: R91.1 U17.7 WP0.1 | length 5.9
  Top Layer w0.5: WP0.1@88.692,125.036 88.751,125.095 90.123,125.095 R91.1@90.504,124.714 90.556,124.662 90.556,122.918 91.554,121.92 U17.7@92.245,121.92
$2N529: Q7.1 R20.2 R21.2 | length 2.7
  Top Layer w0.5: R21.2@143.948,106.934 R20.2@143.948,105.664 143.948,104.26 Q7.1@143.957,104.251
$2N530: Q4.4 Q7.3 R22.1 | length 9.3
  Top Layer w0.5: Q7.3@143.007,102.251 144.023,101.235 144.023,100.838 148.595,100.838 149.484,99.949 Q4.4@149.484,98.32
$2N536: F5.1 R23.2 U7.8 | length 7.5
  Top Layer w0.5: F5.1@149.94,107.95 149.94,106.986 151.389,105.537 U7.8@151.389,103.891
  Top Layer w2: F5.1@149.94,107.95 150.802,108.812 R23.2@152.468,108.812
$2N538: F5.2 Q4.5 Q4.6 Q4.7 Q4.8 | length 6.4
  Top Layer w2: F5.2@146.247,108.667 146.234,108.654 146.234,104.575 Q4.7@146.944,103.864 Q4.6@148.214,103.864
$2N1597: Q8.4 Q16.3 R27.1 | length 7.1
  Top Layer w0.5: R27.1@114.305,102.056 113.364,102.056 112.788,101.48 Q8.4@112.788,99.219 114.797,99.219 Q16.3@115.575,98.441
$2N1603: F6.1 R26.2 U10.8 | length 9.9
  Top Layer w2: R26.2@101.433,93.472 102.807,94.846 102.807,99.627 103.816,100.636 F6.1@105.542,100.636
$2N1605: F6.2 Q8.5 Q8.6 Q8.7 Q8.8
$2N1610: Q9.4 Q20.3 R30.1 | length 7.6
  Top Layer w0.5: R30.1@114.305,111.073 113.11,111.073 112.788,110.751 Q9.4@112.788,108.225 112.788,107.816 112.879,107.725 115.181,107.725 Q20.3@115.575,107.331
$2N1616: F7.1 R29.2 U11.8 | length 7.1
  Top Layer w2: R29.2@101.687,105.41 102.748,106.471 102.748,108.966 103.689,109.907 F7.1@105.415,109.907
$2N1618: F7.2 Q9.5 Q9.6 Q9.7 Q9.8
$2N3421: Q11.1 R40.2 R41.2 | length 3.2
  Top Layer w0.5: R40.2@141.789,119.888 R41.2@143.082,119.888 143.082,119.48 Q11.1@144.123,118.439
$2N3422: Q10.4 Q11.3 R42.1 | length 9.4
  Top Layer w0.5: Q11.3@143.173,116.439 144.023,115.59 144.023,114.681 148.595,114.681 149.484,113.792 Q10.4@149.484,112.29
$2N3428: F8.1 R43.2 U14.8 | length 4.4
  Top Layer w0.5: F8.1@149.94,121.539 149.94,120.396 151.389,118.947 U14.8@151.389,117.777
$2N3430: F8.2 Q10.5 Q10.6 Q10.7 Q10.8 | length 5.7
  Top Layer w2: 146.146,117.885 F8.2@146.146,122.272 ; Q10.7@146.944,117.834 Q10.6@148.214,117.834
$2N4457: Q15.1 R48.2 R49.2 | length 3.2
  Top Layer w0.5: R48.2@141.603,130.824 143.46,130.824 R49.2@143.478,130.842 ; Q15.1@143.495,129.522 R49.2@143.495,130.859
$2N4458: Q14.4 Q15.3 R50.1 | length 8.7
  Top Layer w0.5: Q15.3@142.544,127.508 143.597,127.508 R50.1@144.049,127.056 ; R50.1@144.023,127.052 149.051,127.052 149.484,126.619 Q14.4@149.484,125.244
$2N4464: F10.1 R51.2 U16.8 | length 7.9
  Top Layer w0.5: U16.8@151.389,130.788 151.389,133.051 R51.2@151.688,133.35
  Top Layer w1.5: R51.2@151.688,133.35 152.415,133.35 152.923,133.858 152.923,134.972 F10.1@154.766,136.815
$2N4466: F10.2 Q14.5 Q14.6 Q14.7 Q14.8 | length 8.4
  Top Layer w2: Q14.7@146.944,130.788 Q14.6@148.214,130.788 149.611,132.185 149.611,135.33 F10.2@151.06,136.779
$2N24815: Q16.1 R53.2 R54.2 | length 2.8
  Top Layer w0.5: Q16.1@116.525,100.441 116.525,101.967 R54.2@116.539,101.981 R53.2@116.539,103.251
$2N25317: Q20.1 R55.2 R56.2 | length 5.2
  Top Layer w0.5: R55.2@116.464,111.073 116.464,109.392 116.525,109.331 116.516,109.322 R56.2@116.516,105.918
$2N39826: LED4.1 R64.2 | length 2
  Top Layer w0.5: LED4.1@89.027,91.694 89.57,91.151 R64.2@90.841,91.151
$2N39921: LED5.1 R65.2 | length 2.2
  Top Layer w0.5: LED5.1@89.027,116.586 89.446,117.005 R65.2@91.064,117.005
$2N39926: AV1.2 R26.1 R64.1 U10.7 | length 17.2
  Top Layer w0.5: R64.1@91.064,92.24 91.064,92.794 93.451,95.181 93.927,95.181 ; R26.1@98.475,93.218 98.751,93.218 101.061,95.528 U10.7@101.061,96.669
  Top Layer w2: AV1.2@93.927,98.033 93.927,95.181 95.636,93.472 R26.1@98.475,93.472
$2N39937: AV0.2 R29.1 R65.1 U11.7 | length 19.8
  Top Layer w0.5: R65.1@91.064,116.139 91.064,112.896 AV0.2@93.927,110.032 ; R29.1@98.729,105.537 99.446,105.537 101.061,107.153 U11.7@101.061,108.225
  Top Layer w2: AV0.2@93.927,110.032 93.927,107.119 95.636,105.41 R29.1@98.729,105.41
$2N40038: LED1.1 R61.2 | length 2.2
  Top Layer w0.5: R61.2@164.027,97.8 165.654,97.8 LED1.1@166.087,98.233
$2N40133: LED2.1 R62.2 | length 2.2
  Top Layer w0.5: R62.2@164.027,111.981 165.781,111.981 LED2.1@166.087,112.287
$2N40233: DC3.1 R51.1 R86.2 U16.7 | length 14.1
  Top Layer w0.5: U16.7@152.659,130.788 152.659,131.572 154.437,133.35 R51.1@154.646,133.35 ; R86.2@158.449,126.856 158.449,132.255 DC3.1@159.227,133.033 ; DC3.1@159.155,133.105 DC3.1@159.227,133.176
  Top Layer w2: 155.326,133.35 158.91,133.35 159.155,133.105 DC3.1@159.227,133.033
$2N40244: DC2.1 R43.1 R62.1 U14.7 | length 18.1
  Top Layer w0.5: U14.7@152.659,117.777 152.659,118.928 155.425,121.694 R43.1@155.425,122.443 ; DC2.1@159.227,119.033 163.507,114.753 163.507,113.367 R62.1@164.027,112.847
  Top Layer w2: 157.569,122.443 159.227,120.785 DC2.1@159.227,119.033
$2N40255: DC1.1 R23.1 R61.1 U7.7 | length 20.6
  Top Layer w0.5: U7.7@152.659,103.891 152.659,105.664 155.425,108.43 R23.1@155.425,108.812 ; DC1.1@159.227,105.033 159.227,104.811 163.507,100.531 163.507,99.199 164.027,98.679 R61.1@164.027,98.666
  Top Layer w2: R23.1@155.425,108.812 156.877,108.812 159.227,106.462 DC1.1@159.227,105.033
